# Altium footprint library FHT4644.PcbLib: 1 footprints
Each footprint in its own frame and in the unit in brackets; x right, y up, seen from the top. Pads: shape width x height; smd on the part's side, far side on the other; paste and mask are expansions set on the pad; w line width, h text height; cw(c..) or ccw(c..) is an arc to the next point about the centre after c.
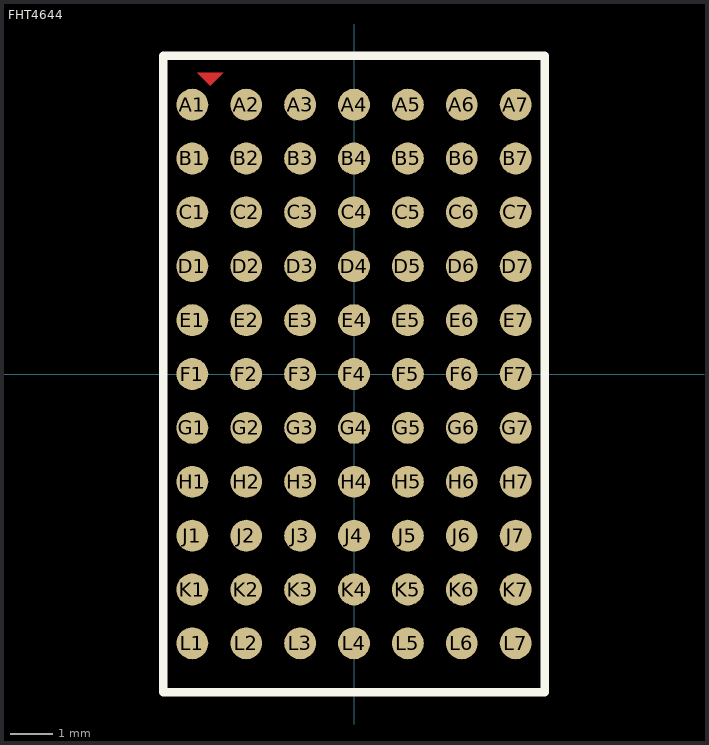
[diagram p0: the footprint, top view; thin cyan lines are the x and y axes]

## FHT4644 [mm]
pads (77):
  round 0.75 smd mask-0.06: A1(-3.81,6.35) A2(-2.54,6.35) A3(-1.27,6.35) A4(0,6.35) A5(1.27,6.35) A6(2.54,6.35) A7(3.81,6.35) B1(-3.81,5.08) B2(-2.54,5.08) B3(-1.27,5.08) B4(0,5.08) B5(1.27,5.08) B6(2.54,5.08) B7(3.81,5.08) C1(-3.81,3.81) C2(-2.54,3.81) C3(-1.27,3.81) C4(0,3.81) C5(1.27,3.81) C6(2.54,3.81) C7(3.81,3.81) D1(-3.81,2.54) D2(-2.54,2.54) D3(-1.27,2.54) D4(0,2.54) D5(1.27,2.54) D6(2.54,2.54) D7(3.81,2.54) E1(-3.81,1.27) E2(-2.54,1.27) E3(-1.27,1.27) E4(0,1.27) E5(1.27,1.27) E6(2.54,1.27) E7(3.81,1.27) F1(-3.81,0) F2(-2.54,0) F3(-1.27,0) F4(0,0) F5(1.27,0) F6(2.54,0) F7(3.81,0) G1(-3.81,-1.27) G2(-2.54,-1.27) G3(-1.27,-1.27) G4(0,-1.27) G5(1.27,-1.27) G6(2.54,-1.27) G7(3.81,-1.27) H1(-3.81,-2.54) H2(-2.54,-2.54) H3(-1.27,-2.54) H4(0,-2.54) H5(1.27,-2.54) H6(2.54,-2.54) H7(3.81,-2.54) J1(-3.81,-3.81) J2(-2.54,-3.81) J3(-1.27,-3.81) J4(0,-3.81) J5(1.27,-3.81) J6(2.54,-3.81) J7(3.81,-3.81) K1(-3.81,-5.08) K2(-2.54,-5.08) K3(-1.27,-5.08) K4(0,-5.08) K5(1.27,-5.08) K6(2.54,-5.08) K7(3.81,-5.08) L1(-3.81,-6.35) L2(-2.54,-6.35) L3(-1.27,-6.35) L4(0,-6.35) L5(1.27,-6.35) L6(2.54,-6.35) L7(3.81,-6.35)
Top Layer:
  region: -3.083,7.1 -3.692,7.1 -3.387,6.795
  region: -3.083,7.103 -3.692,7.103 -3.387,6.798
Top Overlay:
  lines w0.2: -4.5,-7.5 4.5,-7.5 4.5,7.5 -4.5,7.5 -4.5,-7.5
Top Solder:
  region: -3.083,7.102 -3.692,7.102 -3.387,6.797
3D body "FHT4644-3D2.STEP": height 4.8, standoff -0.02, extent -4.499,-7.493 4.501,7.507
